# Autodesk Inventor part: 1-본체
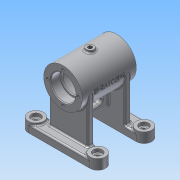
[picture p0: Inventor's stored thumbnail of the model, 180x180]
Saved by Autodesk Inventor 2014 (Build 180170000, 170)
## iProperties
Created: 2015-11
Part Number: 1-본체
Material: 알루미늄 6061
Document SubType Name: Modeling
Designer: 103-09
Density: 2.71 g/cm^3
Appearance: 알루미늄 - 평지
Mass: 359.022 g
Surface Area: 459.449 cm^2
Volume: 132.48 cm^3
Author: 103-09
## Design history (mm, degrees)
sketch "스케치1"
  geometry: L1 (-40, 0)-(40, 0); L2 (-40, 20)-(40, 20); L3 (40, 40)-(-40, 40); L4 (-40, -40)-(40, -40); L5 (40, -20)-(-40, -20); A1 r 10 centre (40, 30) between (40, 20) and (40, 40); A2 r 10 centre (-40, 30) between (-40, 40) and (-40, 20); A3 r 10 centre (40, -30) between (40, -40) and (40, -20); A4 r 10 centre (-40, -30) between (-40, -20) and (-40, -40); 2 further points
  constraints: 10 end point, 8 point on circle, 8 tangent, 4 centre point, 3 parallel, 2 coincident, 1 horizontal, 1 midpoint, 1 vertical alignment
  dimensions: "d2" = 80 distance of A1.centre A2.centre; "d3" = 40 horizontal distance of point (0, 0) A2.centre; "d4" = 20 distance between parallel lines of L2 L3; "d5" = 40 distance between parallel lines of L1 L3; "d6" = 80 distance of A3.centre A4.centre; "d7" = 20 distance between parallel lines of L4 L5; "d8" = 40 distance between parallel lines of L1 L4
extrude "돌출1" new body sketch "스케치1" distance "d9" = 10; taper "d10" = 0 deg
sketch "스케치2"
  geometry: L1 (-40, 20)-(40, 20) reference; L2 (40, 40)-(-40, 40) reference; C1 r 10 at (-40, -30); C2 r 10 at (40, -30); C3 r 10 at (40, 30); C4 r 10 at (-40, 30); A1 r 10 centre (40, -30) between (40, -40) and (40, -20) reference; A2 r 10 centre (-40, -30) between (-40, -20) and (-40, -40) reference; A3 r 10 centre (40, 30) between (40, 20) and (40, 40) reference; A4 r 10 centre (-40, 30) between (-40, 40) and (-40, 20) reference; 1 further point
  constraints: 4 centre point, 4 coincident, 3 equal radius
  dimensions: "d91" = 20 diameter of C4
extrude "돌출2" join sketch "스케치2" distance "d11" = 3; taper "d12" = 0 deg
node "작업 평면1"
sketch "스케치3"
  geometry: L1 (-35, 68)-(35, 68); L2 (-20, 0)-(-40, 0) reference; L3 (-35, 84)-(-23, 84); L4 (-23, 84)-(-23, 82); L5 (-23, 82)-(-21, 82); L6 (-21, 82)-(-21, 89); L7 (-21, 89)-(21, 89); L8 (21, 89)-(21, 82); L9 (21, 82)-(23, 82); L10 (23, 82)-(23, 84); L11 (23, 84)-(35, 84); L12 (35, 84)-(35, 93); L13 (35, 93)-(-35, 93); L14 (-35, 93)-(-35, 84); 2 further points
  constraints: 26 end point, 10 parallel, 3 collinear, 3 vertical alignment, 1 horizontal, 1 midpoint, 1 perpendicular
  dimensions: "d14" = 68 distance between parallel lines of L1 L2; "d15" = 50 diameter of L13 L1; "d16" = 32 diameter of L11 L1; "d17" = 28 diameter of L9 L1; "d18" = 42 diameter of L7 L1; "d19" = 12 distance of L3.start L3.end; "d20" = 70 distance of L12.end L13.end; "d22" = 12 distance of L10.end L11.end; "d23" = 2 distance of L4.end L5.end; "d24" = 42 distance of L6.end L7.end
revolve "회전1" sketch "스케치3" stored, may be unused: angle "d25" = 90 deg
sketch "스케치4"
  geometry: L1 (40, 40)-(-40, 40) reference; L2 (-40, 20)-(40, 20) reference; L3 (-25, 20)-(25, 20); L4 (25, 20)-(25, 28); L5 (25, 28)-(-25, 28); L6 (-25, 28)-(-25, 20); L7 (-40, -40)-(40, -40) reference; L8 (40, -20)-(-40, -20) reference; L9 (-25, -20)-(25, -20); L10 (25, -20)-(25, -28); L11 (25, -28)-(-25, -28); L12 (-25, -28)-(-25, -20); L13 (-4, 20)-(4, 20); L14 (4, -20)-(-4, -20); A1 r 10 centre (-40, -30) between (-40, -20) and (-40, -40) reference; A2 r 10 centre (40, -30) between (40, -40) and (40, -20) reference; 6 further points
  constraints: 20 end point, 5 midpoint, 5 parallel, 3 horizontal, 3 point on line, 3 vertical alignment, 2 equal length, 2 perpendicular, 1 coincident
  dimensions: "d26" = 50 distance of L4.end L5.end; "d27" = 8 distance of L5.end L3.start
extrude "돌출3" join sketch "스케치4" stored distance "d29" = 3; taper "d30" = 0 deg
node "작업 평면4"
sketch "스케치6"
  geometry: L1 (25, 28)-(25, 20) reference; L2 (25, 20)-(-25, 20) reference; L3 (-25, 20)-(-25, 28) reference; L4 (-25, 28)-(25, 28) reference; L5 (25, -20)-(25, -28) reference; L6 (25, -28)-(-25, -28) reference; L7 (-25, -28)-(-25, -20) reference; L8 (-25, -20)-(25, -20) reference; L9 (-4, 20)-(4, 20); L10 (4, 20)-(4, -20); L11 (4, -20)-(-4, -20); L12 (-4, -20)-(-4, 20); 2 further points
  constraints: 8 end point, 2 parallel, 2 point on line, 1 horizontal, 1 midpoint, 1 perpendicular, 1 vertical alignment
  dimensions: "d36" = 8 distance of L9.start L9.end
extrude "돌출5" join sketch "스케치6" stored distance "d37" = 8; taper "d38" = 0 deg
sketch "스케치7"
  geometry: L1 (-20.322, 40)-(0, 40) reference; L2 (-13.5, 12)-(-13.5, 28); L3 (-6.5, 28)-(-6.5, 12); L4 (23, 60)-(23, 40) reference; A1 r 3.5 centre (-10, 28) between (-6.5, 28) and (-13.5, 28); A2 r 3.5 centre (-10, 12) between (-13.5, 12) and (-6.5, 12); 2 further points
  constraints: 4 end point, 4 point on circle, 4 tangent, 2 centre point, 1 horizontal alignment, 1 midpoint, 1 parallel, 1 perpendicular
  dimensions: "d39" = 23 dimension on A1 A2; "d40" = 33 distance from line of A1.centre L4; "d41" = 3.5 radius of A1
extrude "돌출6" cut sketch "스케치7" stored distance "d42" = 8; taper "d43" = 0 deg
node "작업 평면5"
sketch "스케치8"
  geometry: C1 r 5 at (0, 0); 1 further point
  constraints: 1 centre point, 1 coincident
  dimensions: "d45" = 10 diameter of C1
extrude "돌출7" join sketch "스케치8" stored distance "d46" = 8; taper "d47" = 0 deg
node "작업 평면6"
sketch "스케치9"
  geometry: L1 (-4, 23)-(-4, 29.5) reference; L2 (-4, 29.5)-(4, 29.5) reference; L3 (4, 29.5)-(4, 23) reference; L4 (4, 23)-(-4, 23) reference; L5 (-4, 36.5)-(-4, 43.322) reference; L6 (-5, 92.495)-(-5, 96) reference; L7 (-5, 96)-(5, 96) reference; L8 (5, 96)-(5, 92.495) reference; L9 (4, 43.322)-(4, 36.5) reference; L10 (4, 36.5)-(-4, 36.5) reference; L11 (0, 68)-(0, 47); L12 (0, 68)-(14, 43.751); A1 r 25 centre (0, 68) between (-5, 92.495) and (-4, 43.322) reference; A2 r 25 centre (0, 68) between (4, 43.322) and (5, 92.495) reference; 1 further point
  constraints: 4 end point, 1 perpendicular, 1 vertical alignment, 1 other
  dimensions: "d49" = 30 deg angle of L12 L11; "d50" = 28 distance of L11.start L12.end
  node "절단 모서리 투영2"
node "작업 평면7"
sketch "스케치10"
  geometry: C1 r 6 at (0, 0); 1 further point
  constraints: 1 centre point
  dimensions: "d51" = 12 diameter of C1
extrude "돌출8" join sketch "스케치10" stored distance "d52" = 8; taper "d53" = 0 deg
node "작업 평면8"
sketch "스케치11"
  geometry: L1 (-35, 25)-(35, 25) reference; L2 (-35, -25)-(-35, 25) reference; 2 further points
  constraints: 1 other
  dimensions: "d54" = 25 distance from line of L1 point (0, 0); "d55" = 35 distance from line of L2 point (0, 0)
feature "엠보싱1" sketch "스케치11" dims "d56" = 0.5, "d57" = 0
sketch "스케치12"
  geometry: C1 r 25 at (0, 0) reference; C2 r 16 at (0, 0) reference; A1 r 20 centre (0, 0) between (0, 20) and (0, -20); 3 further points
  constraints: 4 point on circle, 2 horizontal alignment, 2 vertical alignment, 1 centre point, 1 coincident
  dimensions: "d58" = 40 diameter of A1
hole "구멍1" sketch "스케치12" at (0, 20), (0, -20), (-20, 0), (20, 0) diameter "d59" = 3.242; stored, may be unused: countersink angle "d63" = 90 deg, drill point angle "d65" = 118 deg; dims "d60" = 8, "d61" = 4, "d62" = 2, "d64" = 10
node "작업 평면9"
hole "구멍2" diameter "d68" = 5.188; stored, may be unused: countersink angle "d72" = 90 deg, drill point angle "d74" = 118 deg; dims "d66" = 10, "d67" = 10, "d69" = 8, "d70" = 4, "d71" = 2, "d73" = 10
hole "구멍3" diameter "d77" = 5.188; stored, may be unused: countersink angle "d81" = 90 deg, drill point angle "d83" = 118 deg; dims "d75" = 10, "d76" = 10, "d78" = 8, "d79" = 4, "d80" = 2, "d82" = 10
chamfer "모따기1" distance "d84" = 1; stored, may be unused: second distance "d85" = 2, angle "d86" = 45 deg
fillet "모깎기1" dims "d87" = 0.3
fillet "모깎기2" dims "d88" = 3
fillet "모깎기3" dims "d89" = 2
fillet "모깎기4" dims "d90" = 2
fillet "모깎기5" dims "d92" = 2
fillet "모깎기6" dims "d93" = 2
fillet "모깎기7" dims "d94" = 2
fillet "모깎기8" dims "d95" = 2
fillet "모깎기9" dims "d96" = 2
fillet "모깎기10" dims "d97" = 2
fillet "모깎기11" dims "d98" = 2
fillet "모깎기12" dims "d99" = 2
fillet "모깎기13" dims "d100" = 2
fillet "모깎기14" dims "d101" = 2
fillet "모깎기15" dims "d102" = 2
fillet "모깎기16" dims "d103" = 2
hole "구멍4" diameter "d106" = 6; stored, may be unused: countersink angle "d110" = 90 deg, drill point angle "d112" = 118 deg; dims "d104" = 10, "d105" = 10, "d107" = 8, "d108" = 12, "d109" = 4, "d111" = 10
fillet "모깎기17" dims "d113" = 0.3
chamfer "모따기2" distance "d114" = 1; stored, may be unused: second distance "d115" = 2, angle "d116" = 45 deg
hole "구멍5" diameter "d119" = 6; stored, may be unused: countersink angle "d123" = 90 deg, drill point angle "d125" = 118 deg; dims "d117" = 10, "d118" = 10, "d120" = 8, "d121" = 12, "d122" = 4, "d124" = 10
hole "구멍6" diameter "d128" = 6; stored, may be unused: countersink angle "d132" = 90 deg, drill point angle "d134" = 118 deg; dims "d126" = 10, "d127" = 10, "d129" = 8, "d130" = 12, "d131" = 4, "d133" = 10
hole "구멍7" diameter "d137" = 6; stored, may be unused: countersink angle "d141" = 90 deg, drill point angle "d143" = 118 deg; dims "d135" = 10, "d136" = 10, "d138" = 8, "d139" = 12, "d140" = 4, "d142" = 10
fillet "모깎기18" dims "d144" = 0.3
chamfer "모따기3" distance "d145" = 1; stored, may be unused: second distance "d146" = 2, angle "d147" = 45 deg
node "솔리드1"
mirror "대칭1"
node "투영된 루프1"
node "투영된 루프2"
node "절단 모서리 투영1"
other parameters: "d13" = 0, "d44" = 96, "d48" = 0
